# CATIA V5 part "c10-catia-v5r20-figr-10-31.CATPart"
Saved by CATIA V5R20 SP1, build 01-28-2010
Part number: Part1
Bounding box of the stored display mesh (mm): x -85.282 to 128.744, y -7.97 to 191.596, z 0 to 148.964
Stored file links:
  D:\v5_r20\psrt_files_downloaded\c10\c10-catia-v5r20-figr-10-31.CATPart
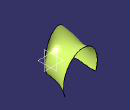
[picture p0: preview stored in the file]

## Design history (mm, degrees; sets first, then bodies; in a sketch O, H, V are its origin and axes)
Set1
  Sketch1 on xy-plane, origin (0, 0, 0), H (1, 0, 0), V (0, 1, 0)
    spline S1 through (-60, 0) (-70, 70) (-70, 170) (-80, 190)
  Sketch2 on yz-plane, origin (0, 0, 0), H (0, 1, 0), V (0, 0, 1)
    spline S1 through (0, 170) (100, 120) (180, 150)
  Sketch3 on xy-plane, origin (0, 0, 0), H (1, 0, 0), V (0, 1, 0)
    spline S1 through (70, 0) (70, 80) (120, 190)
  Sweep1: type Circle, Guide (Sketch1; Sketch2; Sketch3)
Body1 (main body)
